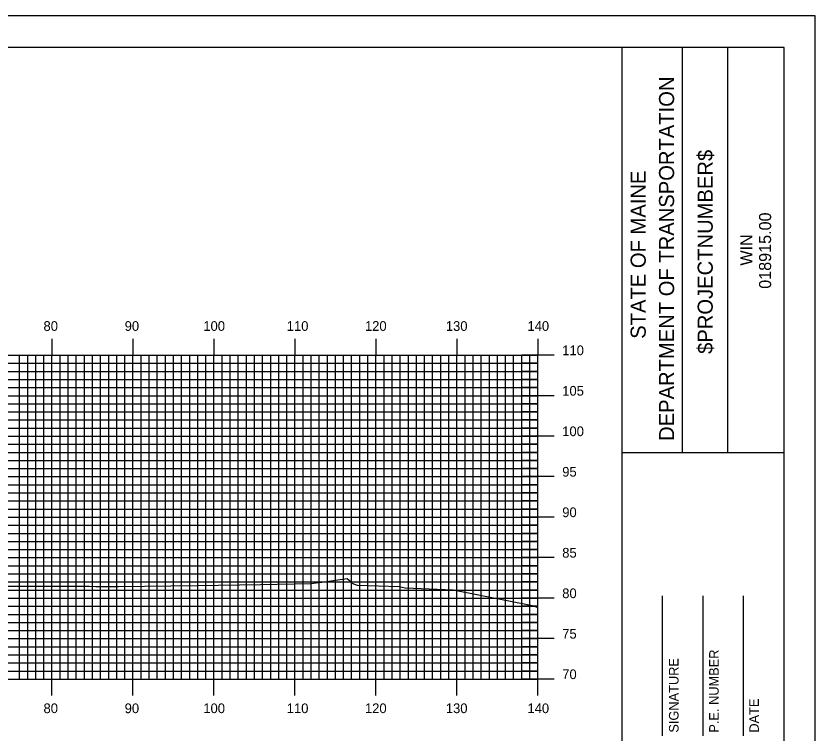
# Model space of a CAD drawing. Extents: x 1758643 to 1758986, y 442591 to 442811.
# Drawn here: x 1758884.2 to 1758982.9, y 442722 to 442810.5 of the extents above; entities that cross this region are included whole.
import ezdxf

# ---------------------------------------------------------------- set-up
doc = ezdxf.new("R2010")
doc.units = 0
for name, color, linetype in [('BORDER', 7, 'Continuous'), ('H_V ANNOTATION', 7, 'Continuous'), ('MAJOR', 7, 'Continuous'), ('MINOR', 7, 'Continuous'), ('PLOT BOUNDARY', 7, 'Continuous'), ('S_Roadway_Centerline', 7, 'Continuous')]:
    doc.layers.add(name, color=color, linetype=linetype)

msp = doc.modelspace()

# ---------------------------------------------------------------- linework, layer by layer
at = {"layer": 'BORDER'}
for p, q in [((1758959.048, 442596.665), (1758959.048, 442806.665)), ((1758966.506, 442756.659), (1758966.506, 442806.659)), ((1758972.096, 442756.659), (1758972.096, 442806.659)), ((1758959.05, 442756.653), (1758979.048, 442756.653)), ((1758964.048, 442721.671), (1758964.048, 442738.966)), ((1758969.048, 442721.671), (1758969.048, 442738.966)), ((1758974.048, 442721.671), (1758974.048, 442738.966))]:
    msp.add_line(p, q, dxfattribs=at)
msp.add_lwpolyline([(1758659.048, 442596.665), (1758979.048, 442596.665), (1758979.048, 442806.665), (1758659.048, 442806.665)], close=True, dxfattribs=at)
at = {"layer": 'MAJOR'}
for p, q in [((1758888.648, 442770.669), (1758888.648, 442768.665)), ((1758898.648, 442770.669), (1758898.648, 442768.665)), ((1758908.648, 442770.669), (1758908.648, 442768.665)), ((1758918.648, 442770.669), (1758918.648, 442768.665)), ((1758928.648, 442770.669), (1758928.648, 442768.665)), ((1758938.648, 442770.669), (1758938.648, 442768.665)), ((1758948.648, 442770.669), (1758948.648, 442768.665)), ((1758668.648, 442768.665), (1758948.648, 442768.665)), ((1758668.648, 442768.665), (1758948.648, 442768.665)), ((1758888.648, 442728.665), (1758888.648, 442768.665)), ((1758898.648, 442728.665), (1758898.648, 442768.665)), ((1758908.648, 442728.665), (1758908.648, 442768.665)), ((1758918.648, 442728.665), (1758918.648, 442768.665)), ((1758928.648, 442728.665), (1758928.648, 442768.665)), ((1758938.648, 442728.665), (1758938.648, 442768.665)), ((1758950.652, 442768.665), (1758946.644, 442768.665)), ((1758948.648, 442728.665), (1758948.648, 442768.665)), ((1758948.648, 442728.665), (1758948.648, 442768.665)), ((1758668.648, 442763.665), (1758948.648, 442763.665)), ((1758950.652, 442763.665), (1758946.644, 442763.665)), ((1758668.648, 442758.665), (1758948.648, 442758.665)), ((1758950.652, 442758.665), (1758946.644, 442758.665)), ((1758668.648, 442753.665), (1758948.648, 442753.665)), ((1758950.652, 442753.665), (1758946.644, 442753.665)), ((1758668.648, 442748.665), (1758948.648, 442748.665)), ((1758950.652, 442748.665), (1758946.644, 442748.665)), ((1758668.648, 442743.665), (1758948.648, 442743.665)), ((1758950.652, 442743.665), (1758946.644, 442743.665)), ((1758668.648, 442738.665), (1758948.648, 442738.665)), ((1758950.652, 442738.665), (1758946.644, 442738.665)), ((1758668.648, 442733.665), (1758948.648, 442733.665)), ((1758950.652, 442733.665), (1758946.644, 442733.665)), ((1758668.648, 442728.665), (1758948.648, 442728.665)), ((1758668.648, 442728.665), (1758948.648, 442728.665)), ((1758888.648, 442726.661), (1758888.648, 442728.665)), ((1758898.648, 442726.661), (1758898.648, 442728.665)), ((1758908.648, 442726.661), (1758908.648, 442728.665)), ((1758918.648, 442726.661), (1758918.648, 442728.665)), ((1758928.648, 442726.661), (1758928.648, 442728.665)), ((1758938.648, 442726.661), (1758938.648, 442728.665)), ((1758950.652, 442728.665), (1758946.644, 442728.665)), ((1758948.648, 442726.661), (1758948.648, 442728.665))]:
    msp.add_line(p, q, dxfattribs=at)
at = {"layer": 'MINOR'}
for p, q in [((1758884.648, 442728.665), (1758884.648, 442768.665)), ((1758885.648, 442728.665), (1758885.648, 442768.665)), ((1758886.648, 442728.665), (1758886.648, 442768.665)), ((1758887.648, 442728.665), (1758887.648, 442768.665)), ((1758889.648, 442728.665), (1758889.648, 442768.665)), ((1758890.648, 442728.665), (1758890.648, 442768.665)), ((1758891.648, 442728.665), (1758891.648, 442768.665)), ((1758892.648, 442728.665), (1758892.648, 442768.665)), ((1758893.648, 442728.665), (1758893.648, 442768.665)), ((1758894.648, 442728.665), (1758894.648, 442768.665)), ((1758895.648, 442728.665), (1758895.648, 442768.665)), ((1758896.648, 442728.665), (1758896.648, 442768.665)), ((1758897.648, 442728.665), (1758897.648, 442768.665)), ((1758899.648, 442728.665), (1758899.648, 442768.665)), ((1758900.648, 442728.665), (1758900.648, 442768.665)), ((1758901.648, 442728.665), (1758901.648, 442768.665)), ((1758902.648, 442728.665), (1758902.648, 442768.665)), ((1758903.648, 442728.665), (1758903.648, 442768.665)), ((1758904.648, 442728.665), (1758904.648, 442768.665)), ((1758905.648, 442728.665), (1758905.648, 442768.665)), ((1758906.648, 442728.665), (1758906.648, 442768.665)), ((1758907.648, 442728.665), (1758907.648, 442768.665)), ((1758909.648, 442728.665), (1758909.648, 442768.665)), ((1758910.648, 442728.665), (1758910.648, 442768.665)), ((1758911.648, 442728.665), (1758911.648, 442768.665)), ((1758912.648, 442728.665), (1758912.648, 442768.665)), ((1758913.648, 442728.665), (1758913.648, 442768.665)), ((1758914.648, 442728.665), (1758914.648, 442768.665)), ((1758915.648, 442728.665), (1758915.648, 442768.665)), ((1758916.648, 442728.665), (1758916.648, 442768.665)), ((1758917.648, 442728.665), (1758917.648, 442768.665)), ((1758919.648, 442728.665), (1758919.648, 442768.665)), ((1758920.648, 442728.665), (1758920.648, 442768.665)), ((1758921.648, 442728.665), (1758921.648, 442768.665)), ((1758922.648, 442728.665), (1758922.648, 442768.665)), ((1758923.648, 442728.665), (1758923.648, 442768.665)), ((1758924.648, 442728.665), (1758924.648, 442768.665)), ((1758925.648, 442728.665), (1758925.648, 442768.665)), ((1758926.648, 442728.665), (1758926.648, 442768.665)), ((1758927.648, 442728.665), (1758927.648, 442768.665)), ((1758929.648, 442728.665), (1758929.648, 442768.665)), ((1758930.648, 442728.665), (1758930.648, 442768.665)), ((1758931.648, 442728.665), (1758931.648, 442768.665)), ((1758932.648, 442728.665), (1758932.648, 442768.665)), ((1758933.648, 442728.665), (1758933.648, 442768.665)), ((1758934.648, 442728.665), (1758934.648, 442768.665)), ((1758935.648, 442728.665), (1758935.648, 442768.665)), ((1758936.648, 442728.665), (1758936.648, 442768.665)), ((1758937.648, 442728.665), (1758937.648, 442768.665)), ((1758939.648, 442728.665), (1758939.648, 442768.665)), ((1758940.648, 442728.665), (1758940.648, 442768.665)), ((1758941.648, 442728.665), (1758941.648, 442768.665)), ((1758942.648, 442728.665), (1758942.648, 442768.665)), ((1758943.648, 442728.665), (1758943.648, 442768.665)), ((1758944.648, 442728.665), (1758944.648, 442768.665)), ((1758945.648, 442728.665), (1758945.648, 442768.665)), ((1758946.648, 442728.665), (1758946.648, 442768.665)), ((1758947.648, 442728.665), (1758947.648, 442768.665)), ((1758668.648, 442767.665), (1758948.648, 442767.665)), ((1758948.648, 442767.665), (1758946.644, 442767.665)), ((1758668.648, 442766.665), (1758948.648, 442766.665)), ((1758948.648, 442766.665), (1758946.644, 442766.665)), ((1758668.648, 442765.665), (1758948.648, 442765.665)), ((1758948.648, 442765.665), (1758946.644, 442765.665)), ((1758668.648, 442764.665), (1758948.648, 442764.665)), ((1758948.648, 442764.665), (1758946.644, 442764.665)), ((1758668.648, 442762.665), (1758948.648, 442762.665)), ((1758948.648, 442762.665), (1758946.644, 442762.665)), ((1758668.648, 442761.665), (1758948.648, 442761.665)), ((1758948.648, 442761.665), (1758946.644, 442761.665)), ((1758668.648, 442760.665), (1758948.648, 442760.665)), ((1758948.648, 442760.665), (1758946.644, 442760.665)), ((1758668.648, 442759.665), (1758948.648, 442759.665)), ((1758948.648, 442759.665), (1758946.644, 442759.665)), ((1758668.648, 442757.665), (1758948.648, 442757.665)), ((1758948.648, 442757.665), (1758946.644, 442757.665)), ((1758668.648, 442756.665), (1758948.648, 442756.665)), ((1758948.648, 442756.665), (1758946.644, 442756.665)), ((1758668.648, 442755.665), (1758948.648, 442755.665)), ((1758948.648, 442755.665), (1758946.644, 442755.665)), ((1758668.648, 442754.665), (1758948.648, 442754.665)), ((1758948.648, 442754.665), (1758946.644, 442754.665)), ((1758668.648, 442752.665), (1758948.648, 442752.665)), ((1758948.648, 442752.665), (1758946.644, 442752.665)), ((1758668.648, 442751.665), (1758948.648, 442751.665)), ((1758948.648, 442751.665), (1758946.644, 442751.665)), ((1758668.648, 442750.665), (1758948.648, 442750.665)), ((1758948.648, 442750.665), (1758946.644, 442750.665)), ((1758668.648, 442749.665), (1758948.648, 442749.665)), ((1758948.648, 442749.665), (1758946.644, 442749.665)), ((1758668.648, 442747.665), (1758948.648, 442747.665)), ((1758948.648, 442747.665), (1758946.644, 442747.665)), ((1758668.648, 442746.665), (1758948.648, 442746.665)), ((1758948.648, 442746.665), (1758946.644, 442746.665)), ((1758668.648, 442745.665), (1758948.648, 442745.665)), ((1758948.648, 442745.665), (1758946.644, 442745.665)), ((1758668.648, 442744.665), (1758948.648, 442744.665)), ((1758948.648, 442744.665), (1758946.644, 442744.665)), ((1758668.648, 442742.665), (1758948.648, 442742.665)), ((1758948.648, 442742.665), (1758946.644, 442742.665)), ((1758668.648, 442741.665), (1758948.648, 442741.665)), ((1758948.648, 442741.665), (1758946.644, 442741.665)), ((1758668.648, 442740.665), (1758948.648, 442740.665)), ((1758948.648, 442740.665), (1758946.644, 442740.665)), ((1758668.648, 442739.665), (1758948.648, 442739.665)), ((1758948.648, 442739.665), (1758946.644, 442739.665)), ((1758668.648, 442737.665), (1758948.648, 442737.665)), ((1758948.648, 442737.665), (1758946.644, 442737.665)), ((1758668.648, 442736.665), (1758948.648, 442736.665)), ((1758948.648, 442736.665), (1758946.644, 442736.665)), ((1758668.648, 442735.665), (1758948.648, 442735.665)), ((1758948.648, 442735.665), (1758946.644, 442735.665)), ((1758668.648, 442734.665), (1758948.648, 442734.665)), ((1758948.648, 442734.665), (1758946.644, 442734.665)), ((1758668.648, 442732.665), (1758948.648, 442732.665)), ((1758948.648, 442732.665), (1758946.644, 442732.665)), ((1758668.648, 442731.665), (1758948.648, 442731.665)), ((1758948.648, 442731.665), (1758946.644, 442731.665)), ((1758668.648, 442730.665), (1758948.648, 442730.665)), ((1758948.648, 442730.665), (1758946.644, 442730.665)), ((1758668.648, 442729.665), (1758948.648, 442729.665)), ((1758948.648, 442729.665), (1758946.644, 442729.665))]:
    msp.add_line(p, q, dxfattribs=at)
at = {"layer": 'PLOT BOUNDARY'}
msp.add_lwpolyline([(1758642.862, 442590.547), (1758982.862, 442590.547), (1758982.862, 442810.547), (1758642.862, 442810.547)], close=True, dxfattribs=at)
at = {"layer": 'S_Roadway_Centerline'}
msp.add_lwpolyline([(1758877.445, 442740.143), (1758893.251, 442740.125), (1758894.06, 442740.103), (1758896.803, 442740.12), (1758906.584, 442740.222), (1758914.388, 442740.353), (1758920.599, 442740.457), (1758921.978, 442740.62), (1758925.08, 442741.091), (1758925.326, 442740.867), (1758925.68, 442740.517), (1758926.325, 442740.247), (1758931.53, 442740.11), (1758932.265, 442739.941), (1758938.197, 442739.688), (1758948.204, 442737.733), (1758948.48, 442737.567), (1758948.648, 442737.607)], dxfattribs=at)

# ---------------------------------------------------------------- texts
at = {"layer": 'BORDER'}
for s, height, p in [('DEPARTMENT OF TRANSPORTATION', 1.86351, (1758965.462, 442758.077)), ('$PROJECTNUMBER$', 1.86351, (1758970.232, 442768.823)), ('STATE OF MAINE', 1.86351, (1758961.959, 442770.689)), ('018915.00', 1.4905, (1758977.439, 442776.861)), ('WIN', 1.4905, (1758975.122, 442779.725)), ('P.E. NUMBER', 1.1811, (1758970.97, 442722.055)), ('SIGNATURE', 1.1811, (1758966.009, 442722.055)), ('DATE', 1.1811, (1758975.931, 442722.055))]:
    msp.add_text(s, height=height, rotation=90, dxfattribs=at).set_placement(p)
at = {"layer": 'H_V ANNOTATION'}
for s, p in [('80', (1758887.599, 442771.665)), ('90', (1758897.621, 442771.665)), ('100', (1758907.332, 442771.665)), ('110', (1758917.632, 442771.665)), ('120', (1758927.289, 442771.665)), ('130', (1758937.278, 442771.665)), ('140', (1758947.353, 442771.665)), ('110', (1758951.648, 442768.665)), ('105', (1758951.648, 442763.665)), ('100', (1758951.648, 442758.665)), ('95', (1758951.648, 442753.665)), ('90', (1758951.648, 442748.665)), ('85', (1758951.648, 442743.665)), ('80', (1758951.648, 442738.665)), ('75', (1758951.648, 442733.665)), ('70', (1758951.648, 442728.665)), ('80', (1758887.599, 442724.465)), ('90', (1758897.621, 442724.465)), ('100', (1758907.332, 442724.465)), ('110', (1758917.632, 442724.465)), ('120', (1758927.289, 442724.465)), ('130', (1758937.278, 442724.465)), ('140', (1758947.353, 442724.465))]:
    msp.add_text(s, height=1.2, dxfattribs=at).set_placement(p)

doc.saveas('drawing.dxf')
